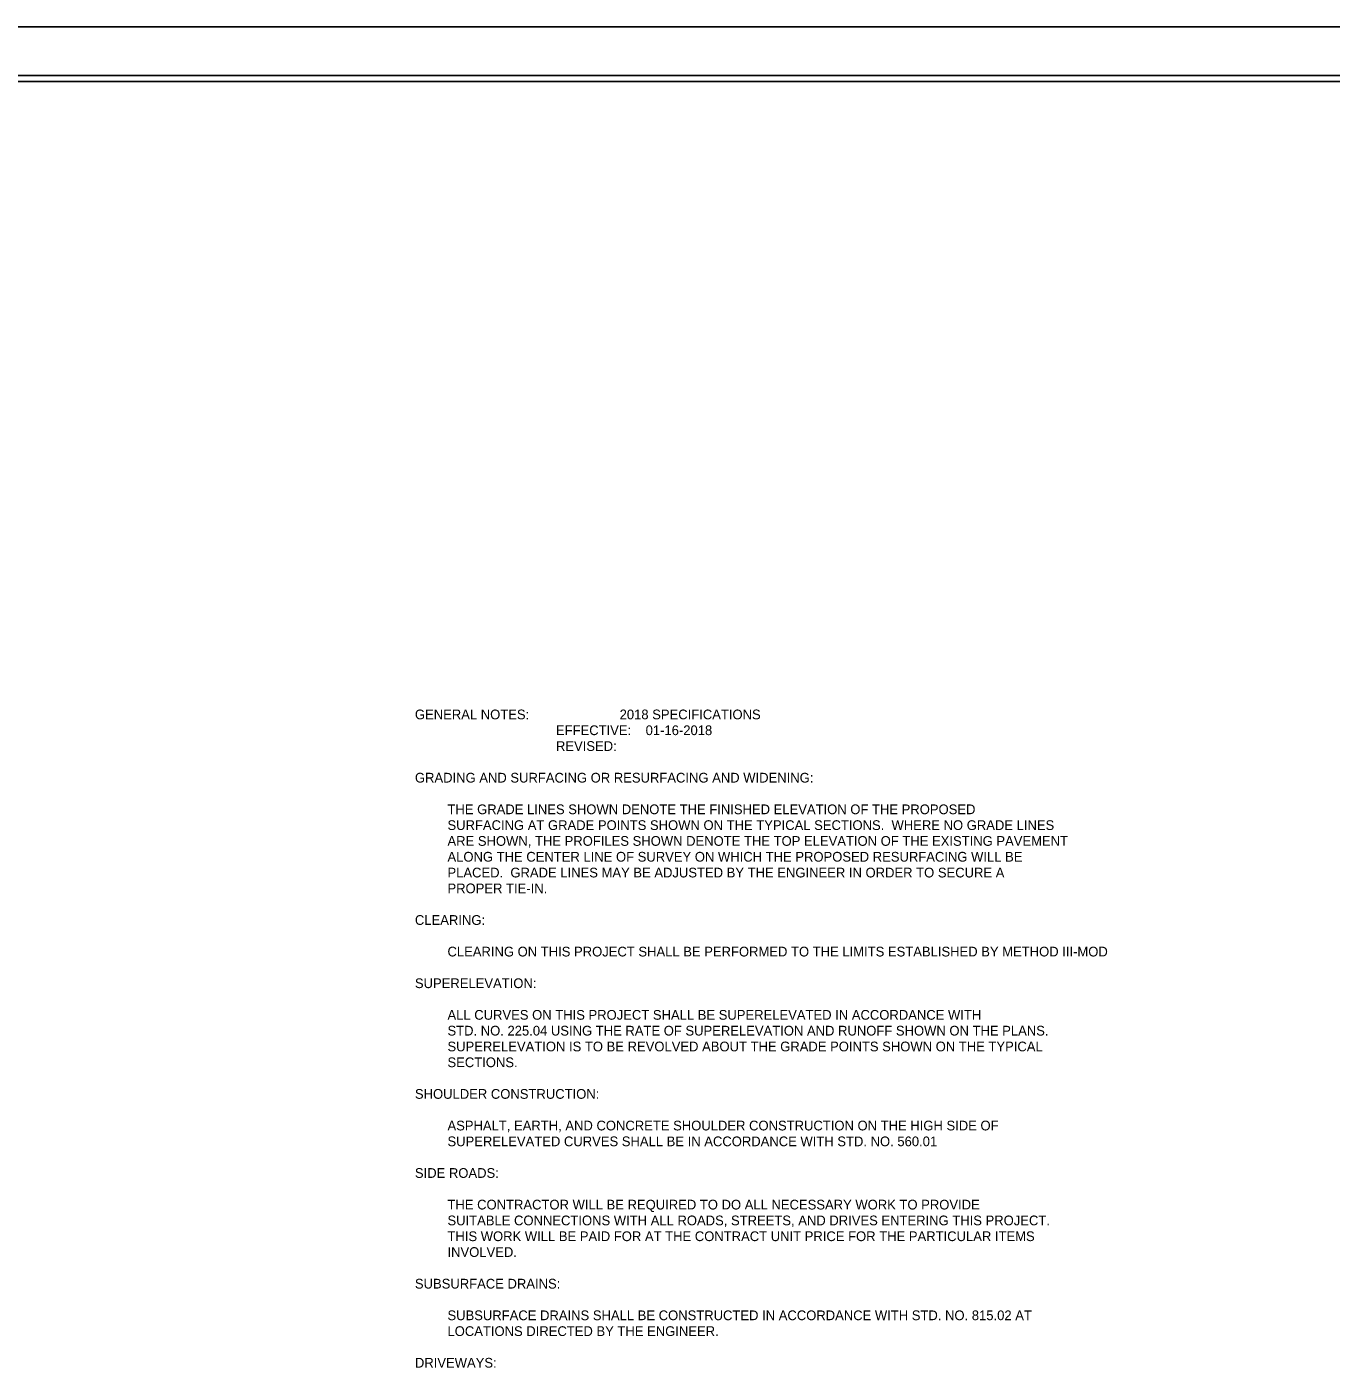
# Model space of a CAD drawing. Extents: x 1983800 to 2121016, y 627229 to 697309.
# Drawn here: x 2018104 to 2052408, y 662023 to 697309 of the extents above; entities that cross this region are included whole.
import ezdxf

# ---------------------------------------------------------------- set-up
doc = ezdxf.new("R2010")
doc.units = 0
for name, color, linetype in [('Sheet Cutting Line CELL', 7, 'Continuous'), ('Sheet Data Text CELL', 7, 'Continuous'), ('Sheet Plan CELL', 7, 'Continuous'), ('Sheet Plot Border Inside CELL', 7, 'Continuous'), ('Sheet Plot Border Outside CELL', 7, 'Continuous')]:
    doc.layers.add(name, color=color, linetype=linetype)

msp = doc.modelspace()

# ---------------------------------------------------------------- linework, layer by layer
at = {"layer": 'Sheet Cutting Line CELL'}
msp.add_line((2091544, 697309), (1983800, 697309), dxfattribs=at)
at = {"layer": 'Sheet Plan CELL'}
msp.add_lwpolyline([(2090456, 695869), (1994456, 695869), (1994456, 628669), (2090456, 628669)], close=True, dxfattribs=at)
at = {"layer": 'Sheet Plot Border Inside CELL'}
msp.add_lwpolyline([(1984632, 628509), (2091256, 628509), (2091256, 696029), (1984632, 696029)], close=True, dxfattribs=at)
at = {"layer": 'Sheet Plot Border Outside CELL'}
msp.add_lwpolyline([(1983800, 627229), (2091544, 627229), (2091544, 697309), (1983800, 697309)], close=True, dxfattribs=at)

# ---------------------------------------------------------------- texts
at = {"layer": 'Sheet Data Text CELL'}
for s, p in [('GENERAL NOTES:                         2018 SPECIFICATIONS', (2028311, 679092)), ('                                       EFFECTIVE:    01-16-2018', (2028311, 678676)), ('                                       REVISED:      ', (2028311, 678260)), ('GRADING AND SURFACING OR RESURFACING AND WIDENING:  ', (2028311, 677428)), ('         THE GRADE LINES SHOWN DENOTE THE FINISHED ELEVATION OF THE PROPOSED ', (2028311, 676596)), ('         SURFACING AT GRADE POINTS SHOWN ON THE TYPICAL SECTIONS.  WHERE NO GRADE LINES ', (2028311, 676180)), ('         ARE SHOWN, THE PROFILES SHOWN DENOTE THE TOP ELEVATION OF THE EXISTING PAVEMENT ', (2028311, 675764)), ('         ALONG THE CENTER LINE OF SURVEY ON WHICH THE PROPOSED RESURFACING WILL BE ', (2028311, 675348)), ('         PLACED.  GRADE LINES MAY BE ADJUSTED BY THE ENGINEER IN ORDER TO SECURE A ', (2028311, 674932)), ('         PROPER TIE-IN.  ', (2028311, 674516)), ('CLEARING:  ', (2028311, 673684)), ('         CLEARING ON THIS PROJECT SHALL BE PERFORMED TO THE LIMITS ESTABLISHED BY METHOD III-MOD', (2028311, 672853)), ('SUPERELEVATION:  ', (2028311, 672021)), ('         ALL CURVES ON THIS PROJECT SHALL BE SUPERELEVATED IN ACCORDANCE WITH', (2028311, 671189)), ('         STD. NO. 225.04 USING THE RATE OF SUPERELEVATION AND RUNOFF SHOWN ON THE PLANS.', (2028311, 670773)), ('         SUPERELEVATION IS TO BE REVOLVED ABOUT THE GRADE POINTS SHOWN ON THE TYPICAL ', (2028311, 670357)), ('         SECTIONS.  ', (2028311, 669941)), ('SHOULDER CONSTRUCTION:  ', (2028311, 669109)), ('         ASPHALT, EARTH, AND CONCRETE SHOULDER CONSTRUCTION ON THE HIGH SIDE OF', (2028311, 668277)), ('         SUPERELEVATED CURVES SHALL BE IN ACCORDANCE WITH STD. NO. 560.01', (2028311, 667861)), ('SIDE ROADS:  ', (2028311, 667029)), ('         THE CONTRACTOR WILL BE REQUIRED TO DO ALL NECESSARY WORK TO PROVIDE ', (2028311, 666197)), ('         SUITABLE CONNECTIONS WITH ALL ROADS, STREETS, AND DRIVES ENTERING THIS PROJECT.  ', (2028311, 665781)), ('         THIS WORK WILL BE PAID FOR AT THE CONTRACT UNIT PRICE FOR THE PARTICULAR ITEMS ', (2028311, 665365)), ('         INVOLVED.  ', (2028311, 664949)), ('SUBSURFACE DRAINS:', (2028311, 664117)), ('         SUBSURFACE DRAINS SHALL BE CONSTRUCTED IN ACCORDANCE WITH STD. NO. 815.02 AT ', (2028311, 663285)), ('         LOCATIONS DIRECTED BY THE ENGINEER.  ', (2028311, 662869)), ('DRIVEWAYS:  ', (2028311, 662037))]:
    msp.add_text(s, height=256, dxfattribs=at).set_placement(p)

doc.saveas('drawing.dxf')
